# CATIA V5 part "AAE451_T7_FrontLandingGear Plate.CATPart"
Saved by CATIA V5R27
Part number: Landing Gear Plate
Bounding box of the stored display mesh (mm): x -12.7 to 12.7, y -100.17 to 100.17, z -150 to 11.538
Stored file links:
  W:\AAE 451\AAE451_T7_FrontLandingGear Plate.CATPart
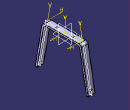
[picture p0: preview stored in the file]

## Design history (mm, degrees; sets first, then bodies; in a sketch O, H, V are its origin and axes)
Body1 (main body)
  Sketch1 on yz-plane, origin (0, 0, 0), H (0, 1, 0), V (0, 0, 1)
    line L1 (-67.467, 0) -> (67.467, 0)
    line L2 (67.467, 0) -> (93.9161, -150)
    point P3 (93.9161, -150)
    line L3 (93.9161, -150) -> (100.1696, -148.8973)
    line L4 (100.1696, -148.8973) -> (72.7953, 6.35)
    line L5 (72.7953, 6.35) -> (-72.7953, 6.35)
    line L6 (-72.7953, 6.35) -> (-100.1696, -148.8973)
    line L7 (-100.1696, -148.8973) -> (-93.9161, -150)
    point P8 (-93.9161, -150)
    line L8 (-93.9161, -150) -> (-67.467, 0)
    angle L2 L3 = 90
    length L3 = 6.35
    length L7 = 6.35
    distance L5 L1 = 6.35
    angle L7 L8 = 90
    distance P3 P8 V = 0
    angle L1 L2 = 100
    angle L1 L8 = 100
    length L5 = 145.5906
    length L2 V = 150
    coincidence: O L1, L1 H
    parallelism: L4 L2, L8 L6
    midpoint: O L1
    horizontal: L5 H
  Pad1: profile Sketch1, direction (1, 0, 0), length 12.7, mirrored extent
  Fillet1: radius 9.525, on edge [face of Pad1 from Sketch1.L1 | face of Pad1 from Sketch1.L8]
  Fillet2: radius 9.525, on edge [face of Pad1 from Sketch1.L2 | face of Pad1 from Sketch1.L1]
  Fillet3: radius 9.525, on edge [face of Pad1 from Sketch1.L5 | face of Pad1 from Sketch1.L4]
  Fillet4: radius 9.525, on edge [face of Pad1 from Sketch1.L6 | face of Pad1 from Sketch1.L5]
  Sketch2 on face of Pad1 from Sketch1.L5, origin (0, 0, 6.35), H (1, 0, 0), V (0, 1, 0)
    point P1 (0, -30)
    point P2 (0, 30)
    distance P2 H = 30
    distance P1 H = 30
    coincidence: P2 V, P1 V
  Sketch3 on face of Pad1 from Sketch1.L5, origin (-9.0852, 38.0144, 6.35), H (1, 0, 0), V (0, 1, 0)
    point P1 (9.0852, -8.0144)
    reference projected point E1 (9.0852, -8.0144) from Sketch2.P2
    coincidence: E1 P1
  Hole1: placed by Sketch3, at (0, 30, 6.35) direction (0, 0, -1), diameter 6.604, up to face of Pad1 from Sketch1.L1
  Sketch4 on face of Pad1 from Sketch1.L5, origin (-8.1603, 6.0174, 6.35), H (1, 0, 0), V (0, 1, 0)
    point P1 (8.1603, -36.0174)
    reference projected point E1 (8.1603, -36.0174) from Sketch2.P1
    coincidence: P1 E1
  Hole2: placed by Sketch4, at (0, -30, 6.35) direction (0, 0, -1), diameter 6.604, up to face of Pad1 from Sketch1.L1
  Sketch5 on face of Pad1 from Sketch1.L8, origin (0, -65.4326, 11.5375), H (-1, 0, 0), V (0, 0.1736, 0.9848)
    point P1 (0, -149.0295)
    reference projected line E1 (12.7, -164.0295) -> (-12.7, -164.0295) from edge [face of Pad1 from Sketch1.L8 | face of Pad1 from Sketch1.L7]
    distance P1 E1 = 15
    coincidence: P1 V
  Sketch6 on face of Pad1 from Sketch1.L2, origin (0, 65.4326, 11.5375), H (1, 0, 0), V (0, -0.1736, 0.9848)
    point P1 (0, -149.0295)
    reference projected line E1 (-12.7, -164.0295) -> (12.7, -164.0295) from edge [face of Pad1 from Sketch1.L3 | face of Pad1 from Sketch1.L2]
    distance P1 E1 = 15
    coincidence: P1 V
  Sketch7 on face of Pad1 from Sketch1.L2, origin (-7.6852, 83.7118, -92.1285), H (1, 0, 0), V (0, -0.1736, 0.9848)
    point P1 (7.6852, -43.7643)
    reference projected point E1 (7.6852, -43.7643) from Sketch6
    coincidence: P1 E1
  Hole3: placed by Sketch7, at (0, 91.3113, -135.2279) direction (0, 0.9848, 0.1736), diameter 6.604, up to face of Pad1 from Sketch1.L4
  Sketch8 on face of Pad1 from Sketch1.L8, origin (-4.6953, -77.0841, -54.541), H (1, 0, 0), V (0, -0.1736, -0.9848)
    point P1 (4.6953, 81.9316)
    reference projected point E1 (4.6953, 81.9316) from Sketch5
    coincidence: P1 E1
  Hole4: placed by Sketch8, at (0, -91.3113, -135.2279) direction (0, -0.9848, 0.1736), diameter 6.604, up to face of Pad1 from Sketch1.L6
  Fillet5: radius 15.875, on edge [face of Pad1 from Sketch1.L8 | face of Pad1 from Sketch1.L7]
  Fillet6: radius 15.875, on edge [face of Pad1 from Sketch1.L2 | face of Pad1 from Sketch1.L1]; edge [face of Pad1 from Sketch1.L5 | face of Pad1 from Sketch1.L4]; edge [face of Pad1 from Sketch1.L6 | face of Pad1 from Sketch1.L5]
  Plane1: type Offset, RefPlane face of Pad1 from Sketch1.L5, Offset 0, reversed
  Sketch9 on xy-plane, origin (0, 0, 0), H (1, 0, 0), V (0, 1, 0)
    point P1 (0, -30)
    point P2 (0, 30)
    distance P2 H = 30
    distance P1 H = 30
    coincidence: P1 V, P2 V
  Sketch10 on face of Pad1 from Sketch1.L1, origin (2.5662, -18.8969, 0), H (1, 0, 0), V (0, -1, 0)
    point P1 (-2.5662, 11.1031)
    reference projected point E1 (-2.5662, 11.1031) from Sketch9.P1
    coincidence: E1 P1
  Hole5: placed by Sketch10, at (0, -30, 0) direction (0, 0, 1), diameter 6.604, up to Plane1
  Sketch11 on face of Pad1 from Sketch1.L1, origin (-3.6037, 27.1597, 0), H (1, 0, 0), V (0, -1, 0)
    point P1 (3.6037, -2.8403)
    reference projected point E1 (3.6037, -2.8403) from Sketch9.P2
    coincidence: E1 P1
  Hole6: placed by Sketch11, at (0, 30, 0) direction (0, 0, 1), diameter 6.604, up to Plane1
  Sketch12 on face of Pad1 from Sketch1.L2, origin (0, 65.4326, 11.5375), H (1, 0, 0), V (0, -0.1736, 0.9848)
    point P1 (0, -154.0295)
    reference projected line E1 (-12.7, -164.0295) -> (12.7, -164.0295) from edge [face of Pad1 from Sketch1.L3 | face of Pad1 from Sketch1.L2]
    distance P1 E1 = 10
    coincidence: P1 V
  Sketch13 on face of Pad1 from Sketch1.L8, origin (0, -65.4326, 11.5375), H (-1, 0, 0), V (0, 0.1736, 0.9848)
    point P1 (0, -154.0295)
    reference projected line E1 (12.7, -164.0295) -> (-12.7, -164.0295) from edge [face of Pad1 from Sketch1.L8 | face of Pad1 from Sketch1.L7]
    distance P1 E1 = 10
    coincidence: P1 V
  Sketch14 on face of Pad1 from Sketch1.L2, origin (1.5844, 89.9543, -127.5316), H (1, 0, 0), V (0, -0.1736, 0.9848)
    point P1 (-1.5844, -12.815)
    reference projected point E1 (-1.5844, -12.815) from Sketch12
    coincidence: P1 E1
  Hole7: placed by Sketch14, at (0, 92.1796, -140.1519) direction (0, 0.9848, 0.1736), diameter 6.604, up to face of Pad1 from Sketch1.L4
  Sketch15 on face of Pad1 from Sketch1.L8, origin (1.811, -85.7518, -103.6983), H (1, 0, 0), V (0, -0.1736, -0.9848)
    point P1 (-1.811, 37.0159)
    reference projected point E1 (-1.811, 37.0159) from Sketch13
    coincidence: E1 P1
  Hole8: placed by Sketch15, at (0, -92.1796, -140.1519) direction (0, -0.9848, 0.1736), diameter 6.604, depth 6.35
Current feature: Hole4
